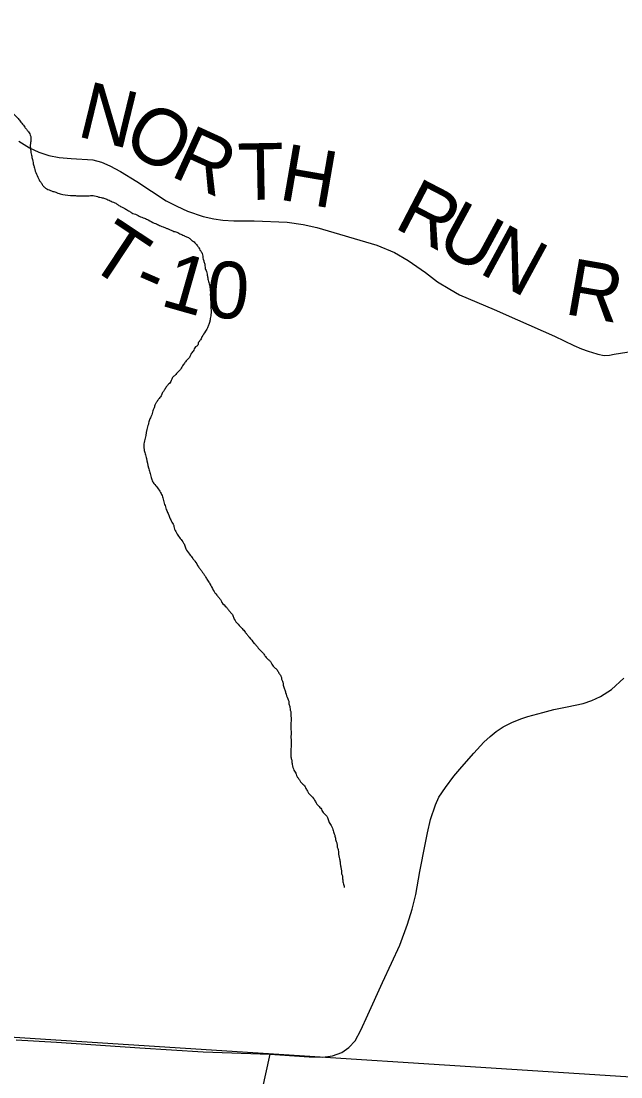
# Model space of a CAD drawing. Extents: x -13.7 to 34, y 0 to 32.3.
# Drawn here: x 25.84 to 26.441, y 15.995 to 17.054 of the extents above; entities that cross this region are included whole.
import ezdxf

# ---------------------------------------------------------------- set-up
doc = ezdxf.new("R2010")
doc.units = 0
for name, color, linetype in [('GM_X_Corporation', 7, 'Continuous'), ('GM_X_Minor_River', 7, 'Continuous'), ('GM_X_State_Route', 7, 'Continuous'), ('GM_X_Township_Road', 7, 'Continuous'), ('GM_X_Township_Road_Text', 7, 'Continuous')]:
    doc.layers.add(name, color=color, linetype=linetype)

msp = doc.modelspace()

# ---------------------------------------------------------------- linework, layer by layer
at = {"layer": 'GM_X_Corporation'}
msp.add_lwpolyline([(25.6876, 16.0444), (26.7165, 15.9781), (26.6464, 14.9606), (25.6185, 15.0191)], close=True, dxfattribs=at)
at = {"layer": 'GM_X_Minor_River'}
for points in [[(25.7482, 17.0535), (25.7517, 17.0522), (25.7547, 17.0513), (25.7581, 17.0501), (25.7607, 17.0492), (25.7641, 17.048), (25.7663, 17.0468), (25.7697, 17.0455), (25.7764, 17.0415), (25.7797, 17.0383), (25.7827, 17.0367), (25.7849, 17.0351), (25.7871, 17.0328), (25.7916, 17.0307), (25.7946, 17.0283), (25.7998, 17.0244), (25.8012, 17.0213), (25.8019, 17.019), (25.8029, 17.0163), (25.8032, 17.0121), (25.803, 17.0076), (25.8013, 17.0023), (25.8005, 17), (25.8, 16.997), (25.7988, 16.9944), (25.7983, 16.9921), (25.7975, 16.9899), (25.8, 16.9867), (25.8015, 16.9844), (25.8041, 16.9824), (25.807, 16.9808), (25.8104, 16.9784), (25.8152, 16.9752), (25.8186, 16.9728), (25.8204, 16.9705), (25.8252, 16.9662), (25.8304, 16.9626), (25.8344, 16.9586), (25.837, 16.9559), (25.8399, 16.9524), (25.8432, 16.9481), (25.8454, 16.9453), (25.8475, 16.9426), (25.8497, 16.938), (25.85, 16.9353), (25.8499, 16.933), (25.8494, 16.9308), (25.8493, 16.9277), (25.8496, 16.9247), (25.8499, 16.922), (25.8506, 16.9193), (25.8509, 16.917), (25.8516, 16.9147), (25.8522, 16.9117), (25.8525, 16.9094), (25.8536, 16.9063), (25.8542, 16.9033), (25.857, 16.8971), (25.8581, 16.8944), (25.8603, 16.8913), (25.8621, 16.8886), (25.8647, 16.8862), (25.8695, 16.8838), (25.8718, 16.8829), (25.874, 16.8825), (25.877, 16.8812), (25.8793, 16.8804), (25.8895, 16.8789), (25.8936, 16.8788), (25.8974, 16.8783), (25.9012, 16.8785), (25.9073, 16.8783), (25.9096, 16.8786), (25.9152, 16.8781), (25.9179, 16.8772), (25.9205, 16.8767), (25.9239, 16.8759), (25.9262, 16.875), (25.9303, 16.873), (25.9351, 16.8709), (25.9374, 16.8693), (25.9407, 16.8673), (25.9433, 16.8661), (25.9467, 16.8641), (25.9489, 16.8629), (25.9511, 16.8613), (25.9534, 16.8605), (25.9586, 16.858), (25.9639, 16.8559), (25.9676, 16.8543), (25.9736, 16.851), (25.9758, 16.8502), (25.9799, 16.8482), (25.9826, 16.8473), (25.9856, 16.8461), (25.9882, 16.8449), (25.9912, 16.8436)], [(25.9912, 16.8436), (25.9934, 16.8428), (25.9972, 16.8415), (25.9994, 16.8403), (26.0031, 16.8387), (26.0058, 16.8374), (26.008, 16.8366), (26.0106, 16.8342), (26.0136, 16.8322), (26.0165, 16.8287), (26.0183, 16.8264), (26.0194, 16.8241), (26.0212, 16.8217), (26.0219, 16.8194), (26.0232, 16.8133), (26.0242, 16.8099), (26.0245, 16.8068), (26.0259, 16.8026), (26.0265, 16.7999), (26.0272, 16.7961), (26.0282, 16.7915), (26.0295, 16.7869), (26.0298, 16.7831), (26.0305, 16.7808), (26.0308, 16.7781), (26.0304, 16.7686), (26.0306, 16.7625), (26.0305, 16.7595), (26.03, 16.7568), (26.0296, 16.7542), (26.0287, 16.7504), (26.0274, 16.7471), (26.025, 16.7426), (26.0214, 16.737), (26.0194, 16.7333), (26.0178, 16.731), (26.0174, 16.7288), (26.015, 16.7269), (26.0126, 16.7228), (26.0102, 16.7195), (26.009, 16.7165), (26.0062, 16.7136), (26.0038, 16.7106), (26.0015, 16.7073), (25.9998, 16.7043), (25.9971, 16.7017), (25.9947, 16.6987), (25.992, 16.6962), (25.9907, 16.6932), (25.988, 16.6895), (25.9856, 16.6869), (25.9836, 16.6835), (25.982, 16.6813), (25.9804, 16.6779), (25.978, 16.6746), (25.976, 16.6716), (25.9744, 16.6694), (25.9735, 16.666), (25.9723, 16.663), (25.9706, 16.6577), (25.9689, 16.654), (25.9677, 16.6495), (25.9668, 16.6468), (25.9645, 16.6355), (25.9632, 16.6299), (25.9631, 16.6272), (25.9634, 16.6242), (25.9644, 16.6199), (25.9658, 16.615), (25.9677, 16.6058), (25.9684, 16.6035), (25.9698, 16.5989), (25.9705, 16.5962), (25.9711, 16.5939), (25.9733, 16.59), (25.9769, 16.5857), (25.9798, 16.5811), (25.982, 16.5768), (25.9826, 16.5745), (25.984, 16.5691), (25.9857, 16.5641), (25.9875, 16.5599), (25.9889, 16.5564), (25.9906, 16.5526), (25.9931, 16.5479), (25.9935, 16.5457), (25.9959, 16.5406), (25.9988, 16.536), (26.0021, 16.5317), (26.0039, 16.5286), (26.0053, 16.5247), (26.0089, 16.5193), (26.0122, 16.515), (26.0144, 16.5123), (26.018, 16.5065), (26.0198, 16.5041), (26.0216, 16.5014)], [(26.0216, 16.5014), (26.0234, 16.4991), (26.0249, 16.4967), (26.027, 16.4932), (26.0295, 16.4894), (26.0328, 16.4832), (26.0364, 16.4781), (26.0386, 16.4754), (26.0404, 16.473), (26.0415, 16.4707), (26.0459, 16.466), (26.048, 16.4633), (26.0502, 16.4609), (26.0524, 16.4578), (26.0538, 16.454), (26.0578, 16.4489), (26.0618, 16.4446), (26.0648, 16.4411), (26.0666, 16.4387), (26.0688, 16.436), (26.0739, 16.4298), (26.0761, 16.4274), (26.0779, 16.4251), (26.083, 16.4196), (26.0852, 16.4165), (26.0878, 16.4137), (26.09, 16.4117), (26.0914, 16.409), (26.0947, 16.4051), (26.0973, 16.4024), (26.0991, 16.3993), (26.1009, 16.3962), (26.1015, 16.3931), (26.1026, 16.3908), (26.1029, 16.3878), (26.1043, 16.3839), (26.1053, 16.3805), (26.1074, 16.3743), (26.1084, 16.372), (26.1087, 16.3693), (26.1097, 16.3655), (26.11, 16.3628), (26.1107, 16.3605), (26.1106, 16.3582), (26.1109, 16.3552), (26.1105, 16.3442), (26.1108, 16.3419), (26.1106, 16.3351), (26.1109, 16.332), (26.1105, 16.321), (26.1107, 16.3161), (26.1114, 16.3126), (26.112, 16.3084), (26.1127, 16.3054), (26.1137, 16.3027), (26.1159, 16.2988), (26.1169, 16.2961), (26.1187, 16.2938), (26.1202, 16.291), (26.1231, 16.2883), (26.1253, 16.2852), (26.1271, 16.2817), (26.1289, 16.279), (26.1333, 16.2743), (26.1354, 16.2708), (26.1372, 16.2681), (26.1405, 16.2645), (26.1431, 16.2603), (26.1474, 16.2552), (26.1485, 16.2514), (26.151, 16.2471), (26.1524, 16.2444), (26.1538, 16.2398), (26.1548, 16.2367), (26.1558, 16.2321), (26.1568, 16.229), (26.1571, 16.2256), (26.1581, 16.2225), (26.1584, 16.2199), (26.1587, 16.2168), (26.1594, 16.2138), (26.16, 16.2096), (26.1606, 16.2057), (26.1613, 16.2023), (26.1615, 16.1992), (26.1622, 16.1969), (26.1625, 16.1939), (26.1631, 16.1897), (26.1638, 16.1874), (26.1641, 16.1851)]]:
    msp.add_spline(points, degree=3, dxfattribs=at)
at = {"layer": 'GM_X_State_Route'}
msp.add_lwpolyline([(25.835, 16.0324), (25.8757, 16.0299), (25.9593, 16.0243), (26.0227, 16.0205), (26.0896, 16.0181), (26.0995, 16.0173), (26.1288, 16.0155), (26.1426, 16.0151), (26.1523, 16.0162), (26.1616, 16.0197), (26.1687, 16.0248), (26.175, 16.0313), (26.1809, 16.0421), (26.1878, 16.0575), (26.2024, 16.0898), (26.2116, 16.1092), (26.2197, 16.1273), (26.2276, 16.1484), (26.2321, 16.1634), (26.2359, 16.178), (26.24, 16.2012), (26.2452, 16.2282), (26.2475, 16.2399), (26.2505, 16.2533), (26.2556, 16.2681), (26.259, 16.2756), (26.2655, 16.2854), (26.2739, 16.2967), (26.282, 16.3061), (26.2942, 16.3199), (26.3039, 16.3308), (26.3104, 16.3365), (26.3165, 16.3416), (26.3234, 16.346), (26.3327, 16.3507), (26.3422, 16.3544), (26.3483, 16.3566), (26.3631, 16.3605), (26.3741, 16.3635), (26.3875, 16.3661), (26.4035, 16.3694), (26.4125, 16.3724), (26.421, 16.3765), (26.4321, 16.3836), (26.4443, 16.3948)], dxfattribs=at)
at = {"layer": 'GM_X_Township_Road'}
for points in [[(25.8379, 16.9333), (25.8486, 16.9265), (25.858, 16.9222), (25.868, 16.919), (25.8782, 16.9167), (25.8904, 16.9158), (25.9121, 16.9145), (25.9207, 16.912), (25.9292, 16.9085), (25.9396, 16.9028), (25.9563, 16.8928), (25.9857, 16.8734), (25.9961, 16.868), (26.007, 16.8631), (26.0228, 16.8578), (26.0332, 16.8553), (26.0424, 16.854), (26.0535, 16.8533), (26.0738, 16.8533), (26.107, 16.852), (26.1228, 16.8497), (26.1365, 16.8466), (26.1968, 16.8288), (26.2145, 16.8216), (26.2283, 16.8135), (26.2456, 16.8017), (26.2577, 16.7923), (26.2699, 16.7847), (26.2797, 16.7793), (26.3144, 16.7644), (26.3377, 16.7542), (26.3748, 16.7378), (26.3944, 16.7284), (26.4019, 16.725), (26.4087, 16.7226), (26.4174, 16.72)], [(26.4174, 16.72), (26.4183, 16.7197), (26.4247, 16.7184), (26.43, 16.7186), (26.4349, 16.7196), (26.4473, 16.7218), (26.4637, 16.7233), (26.4872, 16.7254), (26.504, 16.7263), (26.5266, 16.7286), (26.5528, 16.729), (26.5697, 16.7286)], [(26.0896, 16.0181), (26.0697, 15.9286)]]:
    msp.add_lwpolyline(points, dxfattribs=at)

# ---------------------------------------------------------------- texts
at = {"layer": 'GM_X_Township_Road_Text'}
for s, rotation, p in [('N', 346.2968, (25.8948, 16.9384)), ('O', 328.692, (25.9391, 16.9283)), ('R', 335.4952, (25.9883, 16.8989)), ('T', 1.0712, (26.0577, 16.874)), ('H', 350.2155, (26.0973, 16.875)), ('R', 332.5456, (26.2126, 16.8471)), ('U', 331.5506, (26.2538, 16.8257)), ('T', 326.5465, (25.9043, 16.8097)), ('N', 331.5335, (26.2977, 16.8019)), ('1', 344.1031, (25.9783, 16.769)), ('0', 355.8261, (26.0245, 16.7572)), ('R', 350.1392, (26.3837, 16.7602)), ('-', 336.4229, (25.9491, 16.7811))]:
    msp.add_text(s, height=0.0568, rotation=rotation, dxfattribs=at).set_placement(p)

doc.saveas('drawing.dxf')
